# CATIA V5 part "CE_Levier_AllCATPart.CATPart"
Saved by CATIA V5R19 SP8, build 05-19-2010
Part number: CE2_Levier
Bounding box of the stored display mesh (mm): x -228.5 to 227.5, y -6.065 to 260.935, z 134.697 to 181.297
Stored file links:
  D:\Documents\1_Travail\1 - ac-limoges.fr\ac-limoges.fr\Emmanuel Maynard - STI2D_Turgot\2 -2I2D\1_SEQUENCE_ Tapis_de_course\3- Spécificités\Spé_ITEC\3-Pente\Tapis_TC520B_Pente\CE_Levier_AllCATPart.CATPart
  D:\Documents\1_Travail\1 - ac-limoges.fr\ac-limoges.fr\Emmanuel Maynard - STI2D_Turgot\2 -2I2D\1_SEQUENCE_ Tapis_de_course\3- Spécificités\Spé_ITEC\3-Pente\Tapis_TC520B_Pente\0_Tapis_TC520B_Simulation.CATProduct
  D:\Documents\1_Travail\1 - ac-limoges.fr\ac-limoges.fr\Emmanuel Maynard - STI2D_Turgot\2 -2I2D\1_SEQUENCE_ Tapis_de_course\3- Spécificités\Spé_ITEC\3-Pente\Tapis_TC520B_Pente\CE_Chassis_AllCATPart.CATPart
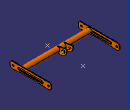
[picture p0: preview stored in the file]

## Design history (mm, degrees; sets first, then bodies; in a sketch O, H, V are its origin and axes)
AxisSystem1: origin (0, 0, 0), X (1, 0, 0), Y (0, 1, 0), Z (0, 0, 1)
Set1
  Plane1: stored without definition
Body1 (main body)
  Sketch1 on Plane1, origin (0, 0, 0), H (0, 1, 0), V (0, 0, 1)
    point P1 (244.2346, 154.9968)
    point P2 (14.2346, 154.9968)
    point P3 (108.2228, 162.6968)
    reference projected circle E1 centre (244.2346, 154.9968) radius 6 from edge [face of Solid1 | face of Solid1]
    reference projected circle E2 centre (108.2228, 162.6968) radius 3.378 from edge [face of Solid4 | face of Solid4]
    reference projected circle E3 centre (14.2346, 154.9968) radius 6 from edge [face of Solid1 | face of Solid1]
    concentricity: P1 E1, P3 E2, E3 P2
Body2 "Part1.1\\Corps principal"
  Solid1: solid without history
Body3 "ecrou_iso_7040-m10-10.1\\ecrou_iso_7040-m10-10"
  Solid2 "Solide.1": solid without history
Body4 "ISO 7089 WASHER 10x20 STEEL GRADE A PLAIN NORMAL SERIES.2\\PartBody"
  Solid3 "Solide.1": solid without history
Body5 "ISO 4014 BOLT M10x60 STEEL GRADE A HEXAGON HEAD.1\\PartBody"
  Solid4 "Solide.1": solid without history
